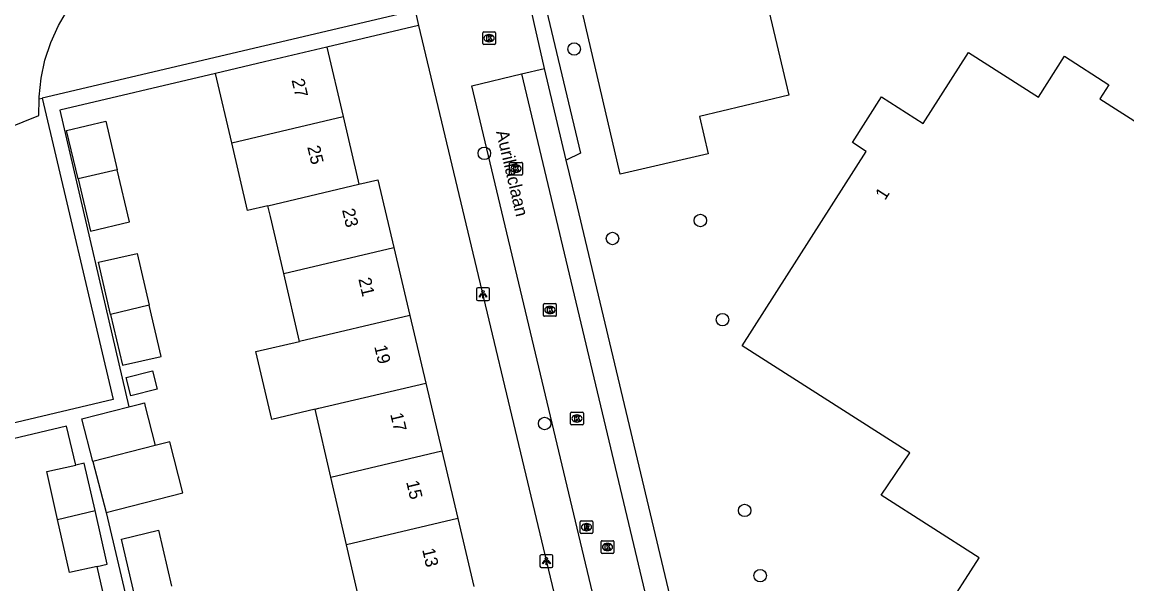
# Model space of a CAD drawing. Extents: x 158474 to 159560, y 388525 to 389605.
# Drawn here: x 159198.5 to 159285.1, y 388605.8 to 388649.8 of the extents above; entities that cross this region are included whole.
import ezdxf

# ---------------------------------------------------------------- set-up
doc = ezdxf.new("R2010")
doc.units = 0
for name, color, linetype in [('IMGEO_Boom', 7, 'Continuous'), ('IMGEO_Groenvoorziening', 7, 'Continuous'), ('IMGEO_Kolk', 7, 'Continuous'), ('IMGEO_Lichtpunt', 7, 'Continuous'), ('IMGEO_Openbare_ruimte_label', 7, 'Continuous'), ('IMGEO_Pand', 7, 'Continuous'), ('IMGEO_Pand_nummerreeks', 7, 'Continuous'), ('IMGEO_Rijbaan_lokaal_open', 7, 'Continuous'), ('IMGEO_Rioolput', 7, 'Continuous'), ('IMGEO_Voetpad_open', 7, 'Continuous')]:
    doc.layers.add(name, color=color, linetype=linetype)

msp = doc.modelspace()

# ---------------------------------------------------------------- linework, layer by layer
at = {"layer": 'IMGEO_Boom'}
for centre in [(159241.765, 388647.713), (159234.728, 388639.536), (159251.659, 388634.265), (159244.768, 388632.858), (159253.394, 388626.481), (159239.452, 388618.341), (159255.129, 388611.523), (159256.348, 388606.411)]:
    msp.add_circle(centre, 0.489, dxfattribs=at)
at = {"layer": 'IMGEO_Groenvoorziening'}
for points in [[(159237.861, 388658.105), (159242.256, 388639.554), (159241.15, 388639.006)], [(159199.819, 388643.8), (159199.82, 388643.968), (159199.978, 388645.419), (159200.286, 388646.845), (159200.742, 388648.231), (159201.34, 388649.562), (159202.074, 388650.824), (159202.936, 388652.001), (159204.476, 388653.608)], [(159168.696, 388616.985), (159195.192, 388623.391), (159195.688, 388623.56), (159196.139, 388623.829), (159196.524, 388624.186), (159196.826, 388624.615), (159197.032, 388625.097), (159197.134, 388625.611), (159197.042, 388626.545), (159194.87, 388640.508), (159199.815, 388642.509), (159199.819, 388643.8)], [(159199.819, 388643.8), (159200.073, 388643.862)]]:
    msp.add_lwpolyline(points, dxfattribs=at)
at = {"layer": 'IMGEO_Kolk'}
for p, q in [((159234.6, 388648.142), (159234.6, 388648.994)), ((159234.675, 388649.068), (159235.527, 388649.068)), ((159235.088, 388648.848), (159235.113, 388648.848)), ((159235.601, 388648.994), (159235.601, 388648.142)), ((159235.527, 388648.068), (159234.675, 388648.068)), ((159235.111, 388648.288), (159235.086, 388648.288)), ((159236.712, 388637.9), (159236.712, 388638.752)), ((159236.787, 388638.826), (159237.639, 388638.826)), ((159237.2, 388638.606), (159237.225, 388638.606)), ((159237.713, 388638.752), (159237.713, 388637.9)), ((159237.639, 388637.826), (159236.787, 388637.826)), ((159237.223, 388638.046), (159237.198, 388638.046)), ((159239.441, 388627.751), (159240.293, 388627.751)), ((159239.366, 388626.825), (159239.366, 388627.677)), ((159239.877, 388626.971), (159239.852, 388626.971)), ((159239.854, 388627.531), (159239.879, 388627.531)), ((159240.367, 388627.677), (159240.367, 388626.825)), ((159240.293, 388626.751), (159239.441, 388626.751)), ((159241.488, 388618.31), (159241.488, 388619.162)), ((159241.563, 388619.236), (159242.415, 388619.236)), ((159242.489, 388619.162), (159242.489, 388618.31)), ((159242.415, 388618.236), (159241.563, 388618.236)), ((159241.999, 388618.456), (159241.974, 388618.456)), ((159241.976, 388619.016), (159242.001, 388619.016)), ((159243.879, 388608.223), (159243.879, 388609.075)), ((159243.954, 388609.149), (159244.806, 388609.149)), ((159244.367, 388608.929), (159244.392, 388608.929)), ((159244.88, 388609.075), (159244.88, 388608.223)), ((159244.806, 388608.149), (159243.954, 388608.149)), ((159244.39, 388608.369), (159244.365, 388608.369))]:
    msp.add_line(p, q, dxfattribs=at)
for points in [[(159234.6, 388648.142), (159234.6, 388648.994)], [(159234.675, 388649.068), (159235.527, 388649.068)], [(159234.921, 388648.768), (159235.044, 388648.768), (159235.044, 388648.617), (159235.174, 388648.768), (159235.338, 388648.768), (159235.192, 388648.617), (159235.345, 388648.368), (159235.193, 388648.368), (159235.108, 388648.532), (159235.044, 388648.465), (159235.044, 388648.368), (159234.921, 388648.368), (159234.921, 388648.768)], [(159235.601, 388648.994), (159235.601, 388648.142)], [(159235.527, 388648.068), (159234.675, 388648.068)], [(159236.712, 388637.9), (159236.712, 388638.752)], [(159236.787, 388638.826), (159237.639, 388638.826)], [(159237.033, 388638.526), (159237.156, 388638.526), (159237.156, 388638.375), (159237.286, 388638.526), (159237.45, 388638.526), (159237.304, 388638.375), (159237.457, 388638.126), (159237.305, 388638.126), (159237.22, 388638.29), (159237.156, 388638.223), (159237.156, 388638.126), (159237.033, 388638.126), (159237.033, 388638.526)], [(159237.713, 388638.752), (159237.713, 388637.9)], [(159237.639, 388637.826), (159236.787, 388637.826)], [(159239.441, 388627.751), (159240.293, 388627.751)], [(159239.366, 388626.825), (159239.366, 388627.677)], [(159239.687, 388627.451), (159239.81, 388627.451), (159239.81, 388627.3), (159239.94, 388627.451), (159240.104, 388627.451), (159239.958, 388627.3), (159240.111, 388627.051), (159239.959, 388627.051), (159239.874, 388627.215), (159239.81, 388627.148), (159239.81, 388627.051), (159239.687, 388627.051), (159239.687, 388627.451)], [(159240.367, 388627.677), (159240.367, 388626.825)], [(159240.293, 388626.751), (159239.441, 388626.751)], [(159241.488, 388618.31), (159241.488, 388619.162)], [(159241.563, 388619.236), (159242.415, 388619.236)], [(159242.489, 388619.162), (159242.489, 388618.31)], [(159242.415, 388618.236), (159241.563, 388618.236)], [(159241.809, 388618.936), (159241.932, 388618.936), (159241.932, 388618.785), (159242.062, 388618.936), (159242.226, 388618.936), (159242.08, 388618.785), (159242.233, 388618.536), (159242.081, 388618.536), (159241.996, 388618.7), (159241.932, 388618.633), (159241.932, 388618.536), (159241.809, 388618.536), (159241.809, 388618.936)], [(159243.879, 388608.223), (159243.879, 388609.075)], [(159243.954, 388609.149), (159244.806, 388609.149)], [(159244.2, 388608.849), (159244.323, 388608.849), (159244.323, 388608.698), (159244.453, 388608.849), (159244.617, 388608.849), (159244.471, 388608.698), (159244.624, 388608.449), (159244.472, 388608.449), (159244.387, 388608.613), (159244.323, 388608.546), (159244.323, 388608.449), (159244.2, 388608.449), (159244.2, 388608.849)], [(159244.88, 388609.075), (159244.88, 388608.223)], [(159244.806, 388608.149), (159243.954, 388608.149)]]:
    msp.add_lwpolyline(points, dxfattribs=at)
for centre, start, end in [((159234.677, 388648.992), 91.55205, 178.44795), ((159234.677, 388648.992), 91.55205, 178.44795), ((159235.525, 388648.992), 1.55205, 88.44795), ((159235.525, 388648.992), 1.55205, 88.44795), ((159234.677, 388648.144), 181.55205, 268.44795), ((159234.677, 388648.144), 181.55205, 268.44795), ((159235.525, 388648.144), 271.55205, 358.44795), ((159235.525, 388648.144), 271.55205, 358.44795), ((159236.789, 388638.75), 91.55205, 178.44795), ((159236.789, 388638.75), 91.55205, 178.44795), ((159237.637, 388638.75), 1.55205, 88.44795), ((159237.637, 388638.75), 1.55205, 88.44795), ((159236.789, 388637.902), 181.55205, 268.44795), ((159236.789, 388637.902), 181.55205, 268.44795), ((159237.637, 388637.902), 271.55205, 358.44795), ((159237.637, 388637.902), 271.55205, 358.44795), ((159239.443, 388627.675), 91.55205, 178.44795), ((159239.443, 388627.675), 91.55205, 178.44795), ((159240.291, 388627.675), 1.55205, 88.44795), ((159240.291, 388627.675), 1.55205, 88.44795), ((159239.443, 388626.827), 181.55205, 268.44795), ((159239.443, 388626.827), 181.55205, 268.44795), ((159240.291, 388626.827), 271.55205, 358.44795), ((159240.291, 388626.827), 271.55205, 358.44795), ((159241.565, 388619.16), 91.55205, 178.44795), ((159241.565, 388619.16), 91.55205, 178.44795), ((159242.413, 388619.16), 1.55205, 88.44795), ((159242.413, 388619.16), 1.55205, 88.44795), ((159241.565, 388618.312), 181.55205, 268.44795), ((159241.565, 388618.312), 181.55205, 268.44795), ((159242.413, 388618.312), 271.55205, 358.44795), ((159242.413, 388618.312), 271.55205, 358.44795), ((159243.956, 388609.073), 91.55205, 178.44795), ((159243.956, 388609.073), 91.55205, 178.44795), ((159244.804, 388609.073), 1.55205, 88.44795), ((159244.804, 388609.073), 1.55205, 88.44795), ((159243.956, 388608.225), 181.55205, 268.44795), ((159243.956, 388608.225), 181.55205, 268.44795), ((159244.804, 388608.225), 271.55205, 358.44795), ((159244.804, 388608.225), 271.55205, 358.44795)]:
    msp.add_arc(centre, 0.0765, start, end, dxfattribs=at)
for centre, major_axis, ratio, start_param, end_param in [((159235.087, 388648.568), (-0.387, 0.002), 0.722429, 4.712389, 7.853982), ((159235.112, 388648.568), (-0.39, 0.002), 0.717154, 1.570796, 4.712389), ((159237.199, 388638.326), (-0.387, 0.002), 0.722429, 4.712389, 7.853982), ((159237.224, 388638.326), (-0.39, 0.002), 0.717154, 1.570796, 4.712389), ((159239.853, 388627.251), (-0.387, 0.002), 0.722429, 4.712389, 7.853982), ((159239.878, 388627.251), (-0.39, 0.002), 0.717154, 1.570796, 4.712389), ((159241.975, 388618.736), (-0.387, 0.002), 0.722429, 4.712389, 7.853982), ((159242, 388618.736), (-0.39, 0.002), 0.717154, 1.570796, 4.712389), ((159244.366, 388608.649), (-0.387, 0.002), 0.722429, 4.712389, 7.853982), ((159244.391, 388608.649), (-0.39, 0.002), 0.717154, 1.570796, 4.712389)]:
    msp.add_ellipse(centre, major_axis=major_axis, ratio=ratio, start_param=start_param, end_param=end_param, dxfattribs=at)
at = {"layer": 'IMGEO_Lichtpunt'}
for p, q in [((159234.124, 388628.884), (159234.124, 388628.077)), ((159234.124, 388628.884), (159234.124, 388628.077)), ((159235.026, 388628.979), (159234.218, 388628.979)), ((159235.026, 388628.979), (159234.218, 388628.979)), ((159235.12, 388628.077), (159235.12, 388628.884)), ((159235.12, 388628.077), (159235.12, 388628.884)), ((159234.218, 388627.983), (159235.026, 388627.983)), ((159234.218, 388627.983), (159235.026, 388627.983)), ((159239.09, 388607.949), (159239.09, 388607.142)), ((159239.09, 388607.949), (159239.09, 388607.142)), ((159239.992, 388608.044), (159239.184, 388608.044)), ((159239.992, 388608.044), (159239.184, 388608.044)), ((159240.086, 388607.142), (159240.086, 388607.949)), ((159240.086, 388607.142), (159240.086, 388607.949)), ((159239.184, 388607.048), (159239.992, 388607.048)), ((159239.184, 388607.048), (159239.992, 388607.048))]:
    msp.add_line(p, q, dxfattribs=at)
for points in [[(159234.498, 388628.548), (159234.537, 388628.52), (159234.349, 388628.258), (159234.311, 388628.285), (159234.498, 388628.548)], [(159234.6, 388628.5), (159234.647, 388628.5), (159234.647, 388628.178), (159234.6, 388628.178), (159234.6, 388628.5)], [(159234.71, 388628.52), (159234.748, 388628.547), (159234.935, 388628.285), (159234.896, 388628.257), (159234.71, 388628.52)], [(159239.464, 388607.613), (159239.503, 388607.585), (159239.315, 388607.323), (159239.277, 388607.35), (159239.464, 388607.613)], [(159239.566, 388607.565), (159239.613, 388607.565), (159239.613, 388607.243), (159239.566, 388607.243), (159239.566, 388607.565)], [(159239.676, 388607.585), (159239.714, 388607.612), (159239.901, 388607.35), (159239.862, 388607.322), (159239.676, 388607.585)]]:
    msp.add_lwpolyline(points, dxfattribs=at)
for centre in [(159234.623, 388628.682), (159239.589, 388607.747)]:
    msp.add_circle(centre, 0.0994, dxfattribs=at)
for centre, start, end in [((159234.218, 388628.884), 90, 180), ((159234.218, 388628.884), 90, 180), ((159235.026, 388628.884), 0, 90), ((159235.026, 388628.884), 0, 90), ((159234.218, 388628.077), 180, 270), ((159234.218, 388628.077), 180, 270), ((159235.026, 388628.077), 270, 0), ((159235.026, 388628.077), 270, 360), ((159239.184, 388607.949), 90, 180), ((159239.184, 388607.949), 90, 180), ((159239.992, 388607.949), 0, 90), ((159239.992, 388607.949), 0, 90), ((159239.184, 388607.142), 180, 270), ((159239.184, 388607.142), 180, 270), ((159239.992, 388607.142), 270, 0), ((159239.992, 388607.142), 270, 360)]:
    msp.add_arc(centre, 0.0946, start, end, dxfattribs=at)
at = {"layer": 'IMGEO_Pand'}
for points in [[(159258.605, 388644.084), (159251.605, 388642.43), (159252.284, 388639.496), (159245.364, 388637.895), (159241.306, 388655.431), (159255.156, 388658.682), (159258.605, 388644.084)], [(159222.372, 388647.85), (159217.506, 388646.704), (159213.644, 388645.794)], [(159222.372, 388647.85), (159223.651, 388642.419)], [(159270.656, 388603.349), (159273.504, 388607.799), (159265.833, 388612.727), (159268.092, 388616.029), (159254.932, 388624.436), (159264.669, 388639.678), (159263.576, 388640.376), (159265.864, 388643.957), (159269.127, 388641.873), (159272.679, 388647.434), (159278.155, 388643.936), (159280.205, 388647.145), (159283.687, 388644.92), (159282.982, 388643.817), (159298.339, 388634.006)], [(159214.923, 388640.363), (159213.644, 388645.794)], [(159202.887, 388637.528), (159201.985, 388641.334), (159205.05, 388642.06), (159205.953, 388638.25)], [(159214.923, 388640.363), (159223.651, 388642.419)], [(159223.651, 388642.419), (159224.765, 388637.688), (159224.844, 388637.353), (159224.902, 388637.104)], [(159217.768, 388635.424), (159216.174, 388635.048), (159214.923, 388640.363)], [(159205.953, 388638.25), (159202.887, 388637.528)], [(159202.887, 388637.528), (159203.858, 388633.431), (159206.923, 388634.157), (159205.953, 388638.25)], [(159224.902, 388637.104), (159226.382, 388637.453), (159227.634, 388632.138)], [(159217.768, 388635.424), (159224.902, 388637.104)], [(159218.999, 388630.103), (159217.966, 388634.571), (159217.768, 388635.424)], [(159218.999, 388630.103), (159227.634, 388632.138)], [(159227.634, 388632.138), (159228.886, 388626.824)], [(159205.426, 388626.904), (159204.481, 388630.987), (159207.513, 388631.689), (159208.456, 388627.618)], [(159220.229, 388624.784), (159218.999, 388630.103)], [(159208.456, 388627.618), (159205.426, 388626.904)], [(159205.426, 388626.904), (159206.352, 388622.907), (159209.384, 388623.609), (159208.456, 388627.618)], [(159228.886, 388626.824), (159220.229, 388624.784)], [(159228.886, 388626.824), (159230.138, 388621.509)], [(159221.459, 388619.464), (159218.069, 388618.665), (159216.817, 388623.98), (159220.229, 388624.784)], [(159206.652, 388621.955), (159208.709, 388622.473), (159209.071, 388621.035), (159207.014, 388620.518), (159206.652, 388621.955)], [(159221.459, 388619.464), (159221.761, 388619.535), (159230.138, 388621.509)], [(159230.138, 388621.509), (159231.39, 388616.195)], [(159206.868, 388619.642), (159207.813, 388619.885), (159208.079, 388619.953), (159208.123, 388619.781), (159208.936, 388616.616)], [(159204.045, 388615.359), (159203.187, 388618.698), (159206.868, 388619.642)], [(159222.688, 388614.145), (159221.459, 388619.464)], [(159208.936, 388616.616), (159204.045, 388615.359)], [(159205.074, 388611.351), (159211.098, 388612.898), (159210.069, 388616.907), (159208.936, 388616.616)], [(159222.688, 388614.145), (159231.39, 388616.195)], [(159231.39, 388616.195), (159232.642, 388610.88)], [(159201.273, 388610.823), (159200.428, 388614.575), (159202.693, 388615.085)], [(159204.209, 388611.522), (159203.372, 388615.238), (159202.693, 388615.085)], [(159204.045, 388615.359), (159205.074, 388611.351)], [(159223.918, 388608.825), (159222.688, 388614.145)], [(159201.273, 388610.823), (159204.209, 388611.522)], [(159204.39, 388607.136), (159205.158, 388607.309), (159204.209, 388611.522)], [(159204.39, 388607.136), (159202.213, 388606.645), (159201.273, 388610.823)], [(159232.642, 388610.88), (159223.918, 388608.825)], [(159232.642, 388610.88), (159233.894, 388605.565)], [(159207.306, 388604.912), (159206.275, 388609.281), (159209.176, 388609.966), (159210.207, 388605.595)], [(159225.149, 388603.504), (159223.918, 388608.825)]]:
    msp.add_lwpolyline(points, dxfattribs=at)
at = {"layer": 'IMGEO_Rijbaan_lokaal_open'}
for points in [[(159247.052, 388576.361), (159242.861, 388593.978), (159245.683, 388594.649), (159233.744, 388644.836), (159237.637, 388645.762)], [(159237.637, 388645.762), (159253.767, 388577.959)]]:
    msp.add_lwpolyline(points, dxfattribs=at)
at = {"layer": 'IMGEO_Rioolput'}
for p, q in [((159242.238, 388609.784), (159242.238, 388610.636)), ((159242.313, 388610.71), (159243.165, 388610.71)), ((159242.726, 388610.49), (159242.751, 388610.49)), ((159243.239, 388610.636), (159243.239, 388609.784)), ((159243.165, 388609.71), (159242.313, 388609.71)), ((159242.749, 388609.93), (159242.724, 388609.93))]:
    msp.add_line(p, q, dxfattribs=at)
for points in [[(159242.238, 388609.784), (159242.238, 388610.636)], [(159242.313, 388610.71), (159243.165, 388610.71)], [(159242.827, 388610.408), (159242.575, 388610.41), (159242.575, 388610.01)], [(159243.239, 388610.636), (159243.239, 388609.784)], [(159243.165, 388609.71), (159242.313, 388609.71)], [(159242.575, 388610.01), (159242.699, 388610.01), (159242.699, 388610.172), (159242.71, 388610.172)], [(159242.753, 388610.329), (159242.699, 388610.329), (159242.699, 388610.248)], [(159242.699, 388610.248), (159242.751, 388610.248)], [(159242.757, 388610.143), (159242.828, 388610.01), (159242.968, 388610.01), (159242.903, 388610.136)]]:
    msp.add_lwpolyline(points, dxfattribs=at)
for centre, radius, start, end in [((159242.315, 388610.634), 0.0765, 91.55205, 178.44795), ((159242.315, 388610.634), 0.0765, 91.55205, 178.44795), ((159242.826, 388610.298), 0.109, 350.36119, 89.41601), ((159243.163, 388610.634), 0.0765, 1.55205, 88.44795), ((159243.163, 388610.634), 0.0765, 1.55205, 88.44795), ((159242.315, 388609.786), 0.0765, 181.55205, 268.44795), ((159242.315, 388609.786), 0.0765, 181.55205, 268.44795), ((159242.709, 388610.119), 0.0533, 26.02933, 88.69889), ((159242.735, 388610.437), 0.19, 274.7715, 282.96867), ((159242.759, 388610.233), 0.0964, 77.00612, 93.18647), ((159242.773, 388610.29), 0.0378, 276.66336, 79.67722), ((159242.824, 388610.298), 0.112, 277.58423, 350.98172), ((159242.808, 388610.083), 0.108, 29.51342, 73.79051), ((159243.163, 388609.786), 0.0765, 271.55205, 358.44795), ((159243.163, 388609.786), 0.0765, 271.55205, 358.44795)]:
    msp.add_arc(centre, radius, start, end, dxfattribs=at)
for centre, major_axis, ratio, start_param, end_param in [((159242.725, 388610.21), (-0.387, 0.002), 0.722429, 4.712389, 7.853982), ((159242.75, 388610.21), (-0.39, 0.002), 0.717154, 1.570796, 4.712389)]:
    msp.add_ellipse(centre, major_axis=major_axis, ratio=ratio, start_param=start_param, end_param=end_param, dxfattribs=at)
at = {"layer": 'IMGEO_Voetpad_open'}
for points in [[(159239.443, 388646.182), (159236.811, 388657.859), (159237.861, 388658.105)], [(159229.294, 388650.743), (159200.073, 388643.862)], [(159229.294, 388650.743), (159229.574, 388649.566)], [(159229.574, 388649.566), (159222.372, 388647.85)], [(159229.574, 388649.566), (159242.23, 388596.442), (159240.949, 388596.135), (159245.514, 388576.124)], [(159237.637, 388645.762), (159239.443, 388646.182)], [(159241.15, 388639.006), (159239.443, 388646.182)], [(159213.644, 388645.794), (159201.454, 388642.922), (159206.868, 388619.642)], [(159200.073, 388643.862), (159205.64, 388620.22), (159169.776, 388611.735)], [(159249.79, 388602.69), (159241.895, 388635.876), (159241.15, 388639.006)], [(159202.693, 388615.085), (159201.971, 388618.129), (159170.055, 388610.56)], [(159205.074, 388611.351), (159210.232, 388589.51), (159227.434, 388593.617)], [(159204.95, 388604.582), (159204.39, 388607.136)]]:
    msp.add_lwpolyline(points, dxfattribs=at)

# ---------------------------------------------------------------- texts
at = {"layer": 'IMGEO_Openbare_ruimte_label'}
msp.add_text('Aurillaclaan', height=1, rotation=283.35534, dxfattribs=at).set_placement((159235.635, 388641.228))
at = {"layer": 'IMGEO_Pand_nummerreeks'}
for s, rotation, p in [('27', 283.25147, (159219.608, 388645.279)), ('25', 283.2523, (159220.843, 388640.03)), ('1', 57.42846, (159266.14, 388635.802)), ('23', 283.25803, (159223.567, 388635.097)), ('21', 283.25517, (159224.845, 388629.676)), ('19', 283.25803, (159226.091, 388624.383)), ('17', 283.25803, (159227.342, 388619.071)), ('15', 283.25517, (159228.594, 388613.76)), ('13', 283.25517, (159229.846, 388608.448))]:
    msp.add_text(s, height=1, rotation=rotation, dxfattribs=at).set_placement(p)

doc.saveas('drawing.dxf')
